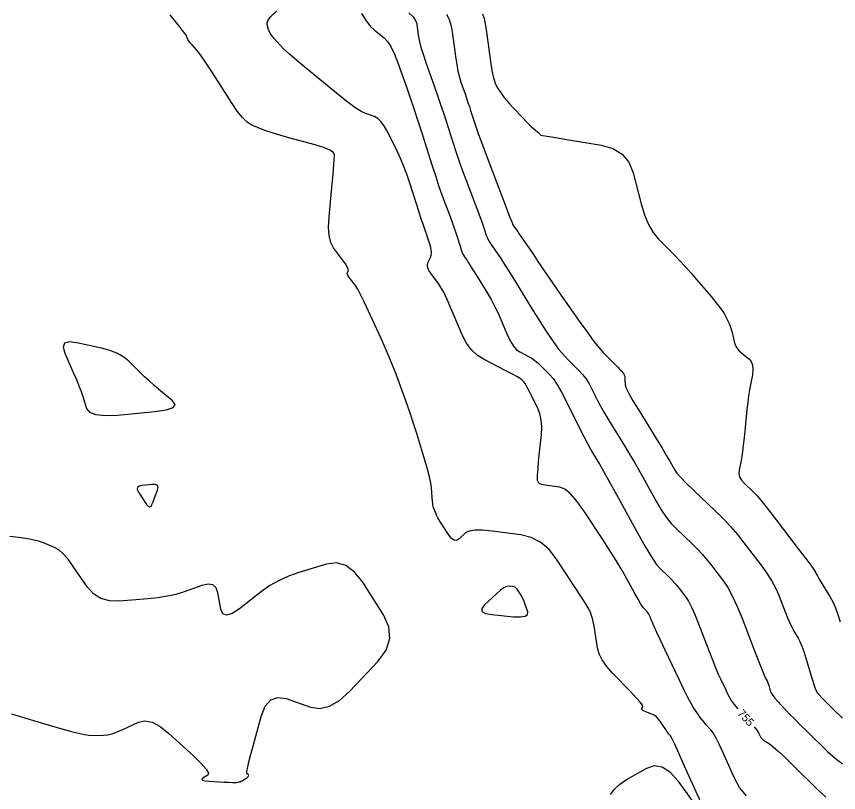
# Model space of a CAD drawing. Extents: x 2082232 to 2083549, y 592624 to 593832.
# Drawn here: x 2082747.4 to 2082819.3, y 592958.7 to 593026.5 of the extents above; entities that cross this region are included whole.
import ezdxf

# ---------------------------------------------------------------- set-up
doc = ezdxf.new("R2010")
doc.units = 0
doc.layers.add('DT_X_Contour_Major', color=7, linetype='Continuous')
doc.layers.add('DT_X_Contour_Minor', color=7, linetype='Continuous')

msp = doc.modelspace()

# ---------------------------------------------------------------- linework, layer by layer
at = {"layer": 'DT_X_Contour_Major'}
for points in [[(2082777.583, 593026.785), (2082777.997, 593026.156), (2082778.372, 593025.677), (2082778.709, 593025.346), (2082779.554, 593024.663), (2082779.868, 593024.336), (2082780.175, 593023.866), (2082780.476, 593023.253), (2082780.77, 593022.498), (2082781.547, 593020.295), (2082781.845, 593019.436), (2082782.157, 593018.512), (2082782.482, 593017.522), (2082782.82, 593016.468), (2082783.74, 593013.568), (2082784.066, 593012.554), (2082784.353, 593011.687), (2082784.601, 593010.967), (2082784.81, 593010.393), (2082785.317, 593009.06), (2082785.497, 593008.58), (2082785.655, 593008.14), (2082785.792, 593007.74), (2082785.909, 593007.379), (2082786.191, 593006.472), (2082786.294, 593006.159), (2082786.392, 593005.899), (2082786.486, 593005.693), (2082786.575, 593005.541), (2082786.806, 593005.207), (2082786.926, 593005.026), (2082787.111, 593004.735), (2082787.362, 593004.333), (2082787.679, 593003.821), (2082788.611, 593002.307), (2082788.945, 593001.742), (2082789.25, 593001.183), (2082789.525, 593000.628), (2082789.77, 593000.079), (2082790.383, 592998.621), (2082790.62, 592998.124), (2082790.871, 592997.728), (2082791.136, 592997.431), (2082791.415, 592997.235), (2082792.179, 592996.845), (2082792.463, 592996.683), (2082792.745, 592996.488), (2082793.023, 592996.261), (2082793.299, 592996.003), (2082794.029, 592995.27), (2082794.322, 592994.922), (2082794.655, 592994.427), (2082795.027, 592993.785), (2082795.437, 592992.996), (2082796.585, 592990.698), (2082796.981, 592989.913), (2082797.307, 592989.281), (2082797.564, 592988.803), (2082797.752, 592988.478), (2082798.16, 592987.816), (2082798.381, 592987.44), (2082798.739, 592986.807), (2082799.234, 592985.919), (2082799.866, 592984.775), (2082801.733, 592981.383), (2082802.38, 592980.238), (2082802.919, 592979.345), (2082803.352, 592978.706), (2082803.678, 592978.319), (2082804.405, 592977.627), (2082804.67, 592977.364), (2082804.92, 592977.098), (2082805.154, 592976.826), (2082805.374, 592976.55), (2082805.94, 592975.808), (2082806.169, 592975.454), (2082806.428, 592974.951), (2082806.719, 592974.298), (2082807.042, 592973.494), (2082807.945, 592971.153), (2082808.262, 592970.339), (2082808.538, 592969.654), (2082808.773, 592969.098), (2082808.966, 592968.671), (2082809.426, 592967.705), (2082809.584, 592967.376), (2082809.715, 592967.115), (2082809.819, 592966.921), (2082809.895, 592966.795), (2082810.061, 592966.549), (2082810.153, 592966.427), (2082810.305, 592966.247), (2082810.486, 592966.043)], [(2082811.903, 592964.494), (2082812.065, 592964.301), (2082812.21, 592964.107), (2082812.292, 592963.966), (2082812.43, 592963.66), (2082812.496, 592963.546), (2082812.592, 592963.434), (2082812.717, 592963.325), (2082812.872, 592963.218), (2082813.323, 592962.935), (2082813.572, 592962.744), (2082813.98, 592962.381), (2082814.547, 592961.849), (2082815.273, 592961.145), (2082817.421, 592959.041), (2082818.165, 592958.338)]]:
    msp.add_lwpolyline(points, dxfattribs=at)
at = {"layer": 'DT_X_Contour_Minor'}
for points in [[(2082807.264, 592957.858), (2082805.8, 592961.116), (2082805.317, 592962.189), (2082804.964, 592962.963), (2082804.743, 592963.438), (2082804.652, 592963.615), (2082804.584, 592963.688), (2082804.54, 592963.744), (2082804.46, 592963.857), (2082804.343, 592964.027), (2082804.189, 592964.254), (2082803.73, 592964.935), (2082803.554, 592965.167), (2082803.369, 592965.355), (2082803.176, 592965.498), (2082802.973, 592965.597), (2082802.423, 592965.798), (2082802.247, 592965.872), (2082802.132, 592965.942), (2082802.078, 592966.009), (2082802.085, 592966.072), (2082802.186, 592966.235), (2082802.147, 592966.364), (2082801.951, 592966.628), (2082801.6, 592967.028), (2082801.094, 592967.563), (2082799.535, 592969.171), (2082799.015, 592969.761), (2082798.621, 592970.324), (2082798.355, 592970.861), (2082798.217, 592971.372), (2082798.016, 592972.698), (2082797.943, 592973.154), (2082797.875, 592973.527), (2082797.811, 592973.817), (2082797.751, 592974.024), (2082797.598, 592974.465), (2082797.471, 592974.726), (2082797.207, 592975.179), (2082796.803, 592975.822), (2082796.262, 592976.657), (2082794.633, 592979.139), (2082793.981, 592979.968), (2082793.244, 592980.596), (2082792.424, 592981.023), (2082791.52, 592981.247), (2082788.999, 592981.577), (2082788.144, 592981.661), (2082787.473, 592981.664), (2082786.984, 592981.587), (2082786.678, 592981.429), (2082786.106, 592980.901), (2082785.89, 592980.771), (2082785.672, 592980.779), (2082785.452, 592980.923), (2082785.229, 592981.204), (2082784.632, 592982.137), (2082784.429, 592982.462), (2082784.267, 592982.738), (2082784.146, 592982.963), (2082784.066, 592983.14), (2082783.908, 592983.543), (2082783.854, 592983.716), (2082783.81, 592983.935), (2082783.774, 592984.197), (2082783.749, 592984.504), (2082783.694, 592985.383), (2082783.643, 592985.78), (2082783.529, 592986.314), (2082783.354, 592986.984), (2082783.118, 592987.789), (2082782.404, 592990.12), (2082782.137, 592990.973), (2082781.871, 592991.787), (2082781.605, 592992.56), (2082781.34, 592993.293), (2082780.635, 592995.194), (2082780.353, 592995.93), (2082780.034, 592996.712), (2082779.68, 592997.54), (2082779.289, 592998.414), (2082778.198, 593000.805), (2082777.819, 593001.616), (2082777.502, 593002.256), (2082777.245, 593002.726), (2082777.05, 593003.025), (2082776.609, 593003.595), (2082776.469, 593003.791), (2082776.378, 593003.952), (2082776.336, 593004.076), (2082776.344, 593004.165), (2082776.431, 593004.353), (2082776.424, 593004.464), (2082776.335, 593004.656), (2082776.167, 593004.927), (2082775.918, 593005.279), (2082775.146, 593006.324), (2082774.903, 593006.788), (2082774.756, 593007.394), (2082774.703, 593008.143), (2082774.745, 593009.035), (2082774.982, 593011.604), (2082775.062, 593012.472), (2082775.123, 593013.149), (2082775.166, 593013.633), (2082775.19, 593013.927), (2082775.23, 593014.455), (2082775.135, 593014.657), (2082774.82, 593014.869), (2082774.285, 593015.09), (2082773.531, 593015.321), (2082771.226, 593015.948), (2082770.428, 593016.171), (2082769.762, 593016.371), (2082769.229, 593016.546), (2082768.828, 593016.698), (2082767.936, 593017.07), (2082767.577, 593017.297), (2082767.169, 593017.699), (2082766.712, 593018.277), (2082766.205, 593019.03), (2082764.789, 593021.271), (2082764.299, 593022.035), (2082763.892, 593022.646), (2082763.568, 593023.104), (2082763.326, 593023.409), (2082762.792, 593024.018), (2082762.615, 593024.225), (2082762.484, 593024.392), (2082762.399, 593024.517), (2082762.36, 593024.602), (2082762.319, 593024.771), (2082762.267, 593024.875), (2082762.142, 593025.059), (2082761.943, 593025.324), (2082761.672, 593025.668), (2082760.849, 593026.694)], [(2082811.243, 592958.445), (2082810.637, 592959.197), (2082810.187, 592960.002), (2082809.192, 592962.217), (2082808.845, 592962.965), (2082808.551, 592963.551), (2082808.309, 592963.972), (2082808.12, 592964.231), (2082807.685, 592964.701), (2082807.522, 592964.886), (2082807.358, 592965.088), (2082807.194, 592965.308), (2082807.028, 592965.545), (2082806.587, 592966.199), (2082806.386, 592966.534), (2082806.11, 592967.049), (2082805.762, 592967.743), (2082805.341, 592968.617), (2082804.119, 592971.185), (2082803.71, 592972.05), (2082803.398, 592972.718), (2082803.184, 592973.189), (2082803.068, 592973.463), (2082802.887, 592973.932), (2082802.823, 592974.092), (2082802.764, 592974.223), (2082802.712, 592974.324), (2082802.667, 592974.395), (2082802.553, 592974.543), (2082802.509, 592974.599), (2082802.462, 592974.653), (2082802.412, 592974.706), (2082802.359, 592974.759), (2082802.214, 592974.897), (2082802.127, 592975.014), (2082801.975, 592975.261), (2082801.758, 592975.638), (2082801.475, 592976.145), (2082800.636, 592977.67), (2082800.281, 592978.292), (2082799.845, 592979.014), (2082799.328, 592979.837), (2082798.73, 592980.759), (2082797.028, 592983.352), (2082796.417, 592984.21), (2082795.862, 592984.839), (2082795.361, 592985.237), (2082794.916, 592985.407), (2082793.801, 592985.553), (2082793.436, 592985.623), (2082793.175, 592985.724), (2082793.019, 592985.856), (2082792.968, 592986.019), (2082792.973, 592986.495), (2082792.983, 592986.737), (2082793.011, 592987.104), (2082793.056, 592987.597), (2082793.119, 592988.216), (2082793.309, 592990.035), (2082793.343, 592990.69), (2082793.3, 592991.291), (2082793.182, 592991.837), (2082792.987, 592992.33), (2082792.368, 592993.571), (2082792.156, 592993.987), (2082791.986, 592994.302), (2082791.858, 592994.518), (2082791.771, 592994.634), (2082791.596, 592994.81), (2082791.455, 592994.91), (2082791.164, 592995.079), (2082790.722, 592995.317), (2082790.13, 592995.624), (2082788.35, 592996.533), (2082787.723, 592996.935), (2082787.176, 592997.457), (2082786.709, 592998.1), (2082786.322, 592998.864), (2082785.398, 593001.062), (2082785.066, 593001.82), (2082784.766, 593002.443), (2082784.497, 593002.933), (2082784.258, 593003.288), (2082783.664, 593004.058), (2082783.479, 593004.334), (2082783.372, 593004.583), (2082783.341, 593004.807), (2082783.388, 593005.004), (2082783.614, 593005.495), (2082783.677, 593005.694), (2082783.695, 593005.921), (2082783.669, 593006.178), (2082783.598, 593006.463), (2082783.35, 593007.261), (2082783.262, 593007.539), (2082783.185, 593007.776), (2082783.118, 593007.972), (2082783.062, 593008.126), (2082782.927, 593008.483), (2082782.854, 593008.689), (2082782.738, 593009.038), (2082782.579, 593009.53), (2082782.376, 593010.167), (2082781.776, 593012.055), (2082781.542, 593012.753), (2082781.287, 593013.428), (2082781.012, 593014.082), (2082780.717, 593014.713), (2082779.903, 593016.368), (2082779.6, 593016.923), (2082779.3, 593017.346), (2082779.003, 593017.637), (2082778.709, 593017.797), (2082777.93, 593018.049), (2082777.553, 593018.231), (2082777.006, 593018.59), (2082776.29, 593019.124), (2082775.404, 593019.835), (2082772.814, 593021.966), (2082771.939, 593022.694), (2082771.257, 593023.28), (2082770.766, 593023.724), (2082770.468, 593024.025), (2082769.928, 593024.641), (2082769.746, 593024.862), (2082769.605, 593025.065), (2082769.506, 593025.249), (2082769.447, 593025.415), (2082769.346, 593025.832), (2082769.338, 593025.992), (2082769.387, 593026.161), (2082769.496, 593026.338), (2082769.663, 593026.523), (2082770.186, 593027.028)], [(2082781.731, 593026.869), (2082782.098, 593026.502), (2082782.224, 593026.341), (2082782.326, 593026.135), (2082782.405, 593025.883), (2082782.459, 593025.585), (2082782.574, 593024.73), (2082782.646, 593024.351), (2082782.777, 593023.855), (2082782.967, 593023.241), (2082783.216, 593022.511), (2082783.958, 593020.406), (2082784.23, 593019.625), (2082784.49, 593018.862), (2082784.737, 593018.117), (2082784.971, 593017.39), (2082785.579, 593015.473), (2082785.82, 593014.736), (2082786.086, 593013.962), (2082786.377, 593013.151), (2082786.694, 593012.303), (2082787.572, 593009.993), (2082787.867, 593009.213), (2082788.093, 593008.606), (2082788.251, 593008.172), (2082788.339, 593007.91), (2082788.485, 593007.442), (2082788.557, 593007.254), (2082788.664, 593007.038), (2082788.808, 593006.794), (2082788.986, 593006.524), (2082789.509, 593005.767), (2082789.751, 593005.404), (2082790.085, 593004.883), (2082790.511, 593004.205), (2082791.029, 593003.368), (2082792.533, 593000.926), (2082793.052, 593000.089), (2082793.479, 592999.411), (2082793.814, 592998.891), (2082794.059, 592998.529), (2082794.589, 592997.775), (2082794.806, 592997.485), (2082795.058, 592997.181), (2082795.344, 592996.862), (2082795.666, 592996.528), (2082796.572, 592995.619), (2082796.895, 592995.269), (2082797.185, 592994.9), (2082797.442, 592994.513), (2082797.666, 592994.106), (2082798.219, 592992.998), (2082798.454, 592992.547), (2082798.744, 592992.029), (2082799.088, 592991.441), (2082799.486, 592990.785), (2082800.622, 592988.943), (2082801.044, 592988.247), (2082801.462, 592987.541), (2082801.874, 592986.824), (2082802.28, 592986.096), (2082803.355, 592984.142), (2082803.769, 592983.443), (2082804.205, 592982.809), (2082804.663, 592982.242), (2082805.142, 592981.742), (2082806.45, 592980.494), (2082806.927, 592980.023), (2082807.377, 592979.542), (2082807.8, 592979.054), (2082808.195, 592978.557), (2082809.214, 592977.22), (2082809.601, 592976.645), (2082809.998, 592975.922), (2082810.405, 592975.05), (2082810.821, 592974.031), (2082811.945, 592971.115), (2082812.319, 592970.149), (2082812.599, 592969.439), (2082812.784, 592968.984), (2082812.874, 592968.785), (2082812.988, 592968.595), (2082813.032, 592968.511), (2082813.078, 592968.401), (2082813.127, 592968.264), (2082813.177, 592968.102), (2082813.316, 592967.634), (2082813.395, 592967.444), (2082813.529, 592967.226), (2082813.719, 592966.98), (2082813.963, 592966.706), (2082814.688, 592965.937), (2082815.008, 592965.603), (2082815.426, 592965.18), (2082815.942, 592964.667), (2082816.554, 592964.064), (2082818.317, 592962.337), (2082818.98, 592961.743), (2082819.644, 592961.256)], [(2082784.998, 593026.736), (2082785.232, 593026.263), (2082785.412, 593025.685), (2082785.538, 593025.003), (2082785.8, 593023.044), (2082785.903, 593022.353), (2082786.015, 593021.749), (2082786.137, 593021.234), (2082786.268, 593020.805), (2082786.629, 593019.78), (2082786.762, 593019.4), (2082786.888, 593019.029), (2082787.008, 593018.666), (2082787.122, 593018.312), (2082787.418, 593017.378), (2082787.574, 593016.918), (2082787.819, 593016.237), (2082788.154, 593015.336), (2082788.577, 593014.213), (2082789.827, 593010.927), (2082790.237, 593009.847), (2082790.531, 593009.073), (2082790.709, 593008.604), (2082790.77, 593008.441), (2082790.779, 593008.413), (2082790.82, 593008.348), (2082790.936, 593008.176), (2082791.129, 593007.896), (2082791.397, 593007.507), (2082792.212, 593006.328), (2082792.491, 593005.922), (2082792.716, 593005.589), (2082792.888, 593005.33), (2082793.007, 593005.144), (2082793.252, 593004.747), (2082793.42, 593004.492), (2082793.74, 593004.025), (2082794.212, 593003.347), (2082794.836, 593002.458), (2082796.702, 592999.805), (2082797.353, 592998.896), (2082797.905, 592998.157), (2082798.358, 592997.591), (2082798.712, 592997.195), (2082799.526, 592996.368), (2082799.801, 592996.086), (2082800.017, 592995.863), (2082800.173, 592995.697), (2082800.27, 592995.588), (2082800.45, 592995.376), (2082800.511, 592995.283), (2082800.558, 592995.164), (2082800.591, 592995.019), (2082800.61, 592994.848), (2082800.643, 592994.357), (2082800.725, 592994.08), (2082800.948, 592993.617), (2082801.31, 592992.968), (2082801.812, 592992.133), (2082803.337, 592989.659), (2082803.85, 592988.823), (2082804.248, 592988.171), (2082804.528, 592987.702), (2082804.693, 592987.417), (2082804.977, 592986.901), (2082805.159, 592986.648), (2082805.491, 592986.273), (2082805.974, 592985.779), (2082806.607, 592985.164), (2082808.495, 592983.362), (2082809.184, 592982.681), (2082809.834, 592981.987), (2082810.445, 592981.281), (2082811.016, 592980.564), (2082812.488, 592978.633), (2082812.998, 592977.929), (2082813.425, 592977.263), (2082813.769, 592976.637), (2082814.03, 592976.049), (2082814.613, 592974.535), (2082814.824, 592974.007), (2082815.017, 592973.558), (2082815.193, 592973.188), (2082815.353, 592972.898), (2082815.755, 592972.229), (2082815.91, 592971.932), (2082816.072, 592971.543), (2082816.243, 592971.063), (2082816.422, 592970.49), (2082816.908, 592968.842), (2082817.084, 592968.283), (2082817.247, 592967.845), (2082817.397, 592967.527), (2082817.533, 592967.329), (2082817.88, 592966.961), (2082818.033, 592966.802), (2082818.233, 592966.6), (2082818.48, 592966.354), (2082818.773, 592966.066), (2082819.616, 592965.24)], [(2082788.157, 593026.774), (2082788.293, 593026.353), (2082788.422, 593025.748), (2082788.543, 593024.961), (2082788.857, 593022.618), (2082788.98, 593021.82), (2082789.114, 593021.182), (2082789.259, 593020.703), (2082789.415, 593020.385), (2082789.844, 593019.751), (2082790.026, 593019.5), (2082790.248, 593019.223), (2082790.512, 593018.92), (2082790.816, 593018.591), (2082791.682, 593017.68), (2082791.982, 593017.367), (2082792.235, 593017.11), (2082792.441, 593016.911), (2082792.598, 593016.768), (2082792.954, 593016.462), (2082793.072, 593016.36), (2082793.158, 593016.284), (2082793.212, 593016.235), (2082793.233, 593016.211), (2082793.249, 593016.181), (2082793.395, 593016.148), (2082793.823, 593016.072), (2082794.532, 593015.953), (2082795.522, 593015.79), (2082798.537, 593015.297), (2082799.559, 593015.008), (2082800.363, 593014.51), (2082800.951, 593013.802), (2082801.321, 593012.886), (2082802.02, 593010.164), (2082802.312, 593009.206), (2082802.666, 593008.375), (2082803.081, 593007.67), (2082803.557, 593007.092), (2082804.908, 593005.718), (2082805.41, 593005.197), (2082805.905, 593004.665), (2082806.392, 593004.121), (2082806.871, 593003.566), (2082808.138, 593002.069), (2082808.568, 593001.552), (2082808.907, 593001.121), (2082809.155, 593000.778), (2082809.312, 593000.521), (2082809.61, 592999.953), (2082809.717, 592999.729), (2082809.814, 592999.485), (2082809.9, 592999.219), (2082809.977, 592998.933), (2082810.167, 592998.14), (2082810.26, 592997.856), (2082810.396, 592997.596), (2082810.574, 592997.362), (2082810.795, 592997.153), (2082811.441, 592996.628), (2082811.642, 592996.394), (2082811.76, 592996.084), (2082811.795, 592995.7), (2082811.748, 592995.24), (2082811.511, 592993.915), (2082811.425, 592993.394), (2082811.345, 592992.827), (2082811.27, 592992.213), (2082811.202, 592991.552), (2082811.026, 592989.728), (2082810.96, 592989.091), (2082810.894, 592988.548), (2082810.829, 592988.1), (2082810.763, 592987.745), (2082810.588, 592986.926), (2082810.567, 592986.622), (2082810.634, 592986.326), (2082810.791, 592986.038), (2082811.037, 592985.757), (2082811.812, 592985.018), (2082812.157, 592984.657), (2082812.609, 592984.129), (2082813.169, 592983.433), (2082813.837, 592982.57), (2082815.762, 592980.046), (2082816.395, 592979.212), (2082816.853, 592978.605), (2082817.133, 592978.223), (2082817.238, 592978.068), (2082817.281, 592977.955), (2082817.328, 592977.864), (2082817.435, 592977.677), (2082817.603, 592977.392), (2082817.832, 592977.01), (2082818.522, 592975.862), (2082818.773, 592975.401), (2082819.01, 592974.878), (2082819.231, 592974.294), (2082819.439, 592973.649)], [(2082759.868, 592993.958), (2082759.431, 592994.327), (2082759.012, 592994.697), (2082758.61, 592995.069), (2082758.226, 592995.442), (2082757.226, 592996.44), (2082756.797, 592996.79), (2082756.258, 592997.092), (2082755.61, 592997.346), (2082754.853, 592997.551), (2082752.689, 592998.034), (2082752.014, 592998.113), (2082751.613, 592997.987), (2082751.485, 592997.657), (2082751.632, 592997.122), (2082752.386, 592995.423), (2082752.65, 592994.816), (2082752.875, 592994.269), (2082753.061, 592993.782), (2082753.207, 592993.355), (2082753.547, 592992.297), (2082753.812, 592991.963), (2082754.349, 592991.756), (2082755.161, 592991.677), (2082756.246, 592991.724), (2082759.504, 592992.019), (2082760.517, 592992.162), (2082761.113, 592992.369), (2082761.293, 592992.64), (2082761.056, 592992.976), (2082759.868, 592993.958)], [(2082759.232, 592983.813), (2082759.246, 592983.856), (2082759.287, 592983.968), (2082759.356, 592984.148), (2082759.453, 592984.396), (2082759.748, 592985.148), (2082759.803, 592985.392), (2082759.746, 592985.557), (2082759.577, 592985.643), (2082759.297, 592985.652), (2082758.402, 592985.571), (2082758.129, 592985.512), (2082757.983, 592985.397), (2082757.963, 592985.225), (2082758.07, 592984.996), (2082758.524, 592984.312), (2082758.676, 592984.085), (2082758.792, 592983.918), (2082758.872, 592983.812), (2082758.915, 592983.766), (2082758.984, 592983.723), (2082759.01, 592983.711), (2082759.037, 592983.705), (2082759.065, 592983.707), (2082759.094, 592983.715), (2082759.173, 592983.747), (2082759.199, 592983.758), (2082759.217, 592983.769), (2082759.228, 592983.779), (2082759.232, 592983.789), (2082759.232, 592983.813)], [(2082773.119, 592966.212), (2082773.932, 592966.093), (2082774.776, 592966.286), (2082775.652, 592966.791), (2082776.559, 592967.608), (2082779.018, 592970.202), (2082779.739, 592971.186), (2082780.06, 592972.193), (2082779.981, 592973.222), (2082779.5, 592974.275), (2082777.685, 592977.111), (2082776.976, 592978.007), (2082776.211, 592978.57), (2082775.389, 592978.798), (2082774.51, 592978.692), (2082772.092, 592977.965), (2082771.208, 592977.657), (2082770.371, 592977.276), (2082769.58, 592976.823), (2082768.835, 592976.298), (2082766.91, 592974.802), (2082766.267, 592974.378), (2082765.78, 592974.228), (2082765.451, 592974.353), (2082765.278, 592974.752), (2082765.026, 592976.182), (2082764.867, 592976.624), (2082764.579, 592976.878), (2082764.162, 592976.945), (2082763.616, 592976.823), (2082761.987, 592976.248), (2082761.336, 592976.05), (2082760.605, 592975.888), (2082759.795, 592975.761), (2082758.905, 592975.67), (2082756.425, 592975.476), (2082755.553, 592975.497), (2082754.797, 592975.706), (2082754.156, 592976.104), (2082753.632, 592976.69), (2082752.387, 592978.504), (2082751.933, 592979.118), (2082751.508, 592979.599), (2082751.11, 592979.948), (2082750.741, 592980.164), (2082749.791, 592980.563), (2082749.34, 592980.709), (2082748.699, 592980.848), (2082747.868, 592980.981), (2082746.847, 592981.107)], [(2082790.878, 592974.105), (2082791.488, 592974.08), (2082791.896, 592974.14), (2082792.103, 592974.286), (2082792.108, 592974.519), (2082791.853, 592975.252), (2082791.759, 592975.51), (2082791.666, 592975.732), (2082791.575, 592975.92), (2082791.485, 592976.072), (2082791.249, 592976.432), (2082791.155, 592976.552), (2082791.048, 592976.643), (2082790.929, 592976.705), (2082790.798, 592976.738), (2082790.432, 592976.786), (2082790.264, 592976.756), (2082790.032, 592976.633), (2082789.737, 592976.415), (2082789.379, 592976.102), (2082788.341, 592975.144), (2082788.089, 592974.821), (2082788.112, 592974.57), (2082788.41, 592974.393), (2082788.983, 592974.288), (2082790.878, 592974.105)], [(2082746.983, 592965.618), (2082748.115, 592965.277), (2082751.187, 592964.371), (2082752.235, 592964.076), (2082753.078, 592963.867), (2082753.714, 592963.747), (2082754.145, 592963.714), (2082755.018, 592963.742), (2082755.369, 592963.782), (2082755.768, 592963.879), (2082756.214, 592964.033), (2082756.709, 592964.246), (2082758.09, 592964.888), (2082758.643, 592965.007), (2082759.269, 592964.883), (2082759.966, 592964.514), (2082760.735, 592963.901), (2082762.88, 592961.943), (2082763.563, 592961.287), (2082764.002, 592960.789), (2082764.197, 592960.449), (2082764.149, 592960.267), (2082763.697, 592959.99), (2082763.607, 592959.896), (2082763.677, 592959.822), (2082763.908, 592959.767), (2082764.298, 592959.731), (2082765.552, 592959.66), (2082765.974, 592959.639), (2082766.3, 592959.628), (2082766.528, 592959.626), (2082766.659, 592959.635), (2082766.881, 592959.671), (2082766.967, 592959.692), (2082767.061, 592959.729), (2082767.161, 592959.78), (2082767.269, 592959.846), (2082767.566, 592960.043), (2082767.657, 592960.114), (2082767.708, 592960.178), (2082767.719, 592960.234), (2082767.69, 592960.284), (2082767.559, 592960.407), (2082767.552, 592960.579), (2082767.63, 592961.001), (2082767.793, 592961.674), (2082768.041, 592962.598), (2082768.815, 592965.396), (2082769.168, 592966.28), (2082769.649, 592966.833), (2082770.256, 592967.055), (2082770.991, 592966.945), (2082773.119, 592966.212)], [(2082799.356, 592958.579), (2082799.688, 592959.046), (2082800.155, 592959.477), (2082800.756, 592959.873), (2082802.538, 592960.882), (2082803.207, 592961.096), (2082803.877, 592960.982), (2082804.548, 592960.541), (2082805.221, 592959.771), (2082807.015, 592957.282)]]:
    msp.add_lwpolyline(points, dxfattribs=at)

# ---------------------------------------------------------------- texts
at = {"layer": 'DT_X_Contour_Major'}
msp.add_text('755', height=0.7, rotation=312.43437, dxfattribs=at).set_placement((2082810.404, 592965.618))

doc.saveas('drawing.dxf')
